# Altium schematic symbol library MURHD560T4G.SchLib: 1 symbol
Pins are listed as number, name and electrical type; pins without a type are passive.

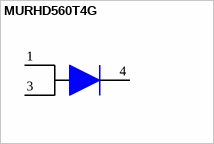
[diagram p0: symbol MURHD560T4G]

## MURHD560T4G
designator D?
Ultra-Fast Diode 600V, 5A, DPAK; Manufacturer: ON Semiconductor
footprint DPAK (Footprint not found)
pins: 1, 3, 4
